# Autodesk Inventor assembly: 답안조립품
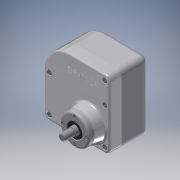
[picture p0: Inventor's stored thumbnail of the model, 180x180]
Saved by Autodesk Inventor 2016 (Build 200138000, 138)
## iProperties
Created: 2015-11
Part Number: 답안조립품
Document SubType Name: Assembly
Designer: Administrator
Author: Administrator
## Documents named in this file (13)
- C:\Users\Administrator\Downloads\Inventor2급\2급\공용부품_20151104_2\답안조립품.iam
- C:\Users\Administrator\Downloads\Inventor2급\2급\공용부품_20151104_2\1-본체.ipt
- C:\Users\Administrator\Downloads\Inventor2급\2급\공용부품_20151104_2\로드 축.ipt
- C:\Users\Administrator\Downloads\Inventor2급\2급\공용부품_20151104_2\로드.ipt
- C:\Users\Administrator\Downloads\Inventor2급\2급\공용부품_20151104_2\베어링 6001.ipt
- C:\Users\Administrator\Downloads\Inventor2급\2급\공용부품_20151104_2\베어링 6002.ipt
- C:\Users\Administrator\Downloads\Inventor2급\2급\공용부품_20151104_2\앞커버.ipt
- C:\Users\Administrator\Downloads\Inventor2급\2급\공용부품_20151104_2\오일실 15 x 25.ipt
- C:\Users\Administrator\Downloads\Inventor2급\2급\공용부품_20151104_2\오일실 12 x 22.ipt
- C:\Users\Administrator\Downloads\Inventor2급\2급\공용부품_20151104_2\축 커버.ipt
- C:\Users\Administrator\Downloads\Inventor2급\2급\공용부품_20151104_2\편심 축.ipt
- C:\Users\Administrator\Downloads\Inventor2급\2급\공용부품_20151104_2\M3 x 0.5.ipt
- C:\Users\Administrator\Downloads\Inventor2급\2급\공용부품_20151104_2\M4 x 0.7.ipt
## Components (10 placed, 3 different names)
1. 1-본체:1 — Mate:1, Mate:2, Mate:4, Mate:5, Mate:7, Mate:8, Mate:9, Mate:10, Mate:11, Mate:20, Mate:22, Mate:27, Insert:2, Insert:3, Insert:4, Insert:5, Insert:6
2. M4 x 0.7:1 — Insert:2
3. M4 x 0.7:2 — Insert:3
4. M4 x 0.7:3 — Insert:4
5. M4 x 0.7:4 — Insert:5
6. M4 x 0.7:5 — Insert:6
7. M3 x 0.5:1 — Insert:1
8. M3 x 0.5:2
9. M3 x 0.5:3
10. M3 x 0.5:4
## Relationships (18: Mate 12, Insert 6)
- Mate:1: 1-본체:1
- Mate:2: 1-본체:1
- Mate:4: 1-본체:1
- Mate:5: 1-본체:1
- Mate:7: 1-본체:1
- Mate:8: 1-본체:1
- Mate:9: 1-본체:1
- Mate:10: 1-본체:1
- Mate:11: 1-본체:1
- Mate:20: 1-본체:1
- Mate:22: 1-본체:1
- Mate:27: 1-본체:1
- Insert:1: M3 x 0.5:1
- Insert:2: 1-본체:1 ↔ M4 x 0.7:1
- Insert:3: 1-본체:1 ↔ M4 x 0.7:2
- Insert:4: 1-본체:1 ↔ M4 x 0.7:3
- Insert:5: 1-본체:1 ↔ M4 x 0.7:4
- Insert:6: 1-본체:1 ↔ M4 x 0.7:5
